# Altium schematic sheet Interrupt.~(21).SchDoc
size A; SheetNumber: 1; SheetTotal: 1
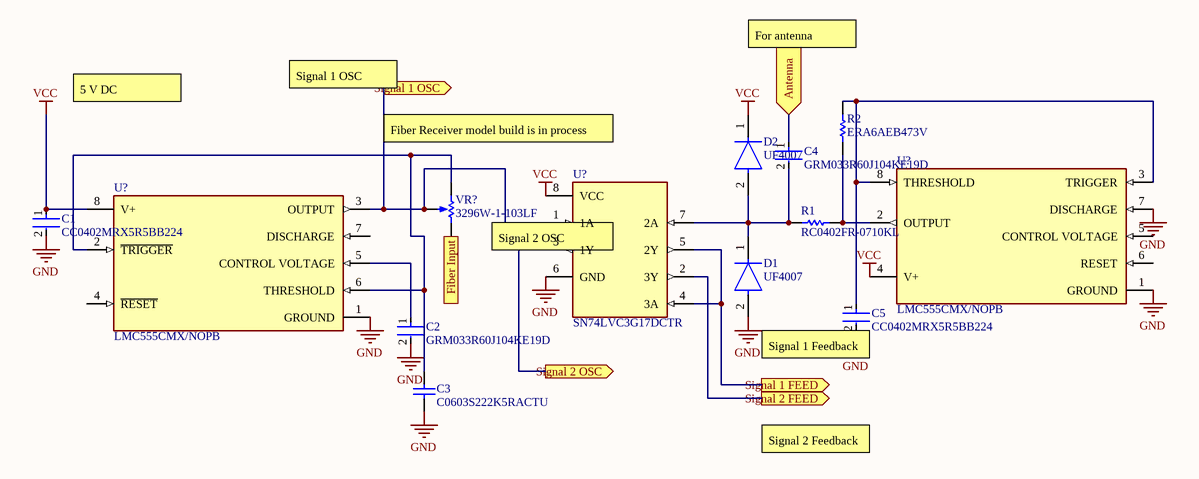
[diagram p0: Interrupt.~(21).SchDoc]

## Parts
(Parts that share a designator on the sheet are numbered #1, #2 ... from top to bottom, then left to right.)
C1  CC0402MRX5R5BB224  [FP-CC0402-MFG]
C2  GRM033R60J104KE19D  [FP-GRM033-0_03-MFG]
C3  C0603S222K5RACTU  [CAPC1608X87X35NL15T15]
C4  GRM033R60J104KE19D  [FP-GRM033-0_03-MFG]
C5  CC0402MRX5R5BB224  [FP-CC0402-MFG]
D1  UF4007  [FP-017AH-MFG]
D2  UF4007  [FP-017AH-MFG]
R1  RC0402FR-0710KL  [RESC1005X40X25LL05T10]
R2  ERA6AEB473V  [RESC2013X60X40LL20T25]
U?#1  LMC555CMX/NOPB  [FP-D0008A-MFG]
U?#2  SN74LVC3G17DCTR  [FP-DCT0008A-MFG]
U?#3  LMC555CMX/NOPB  [FP-D0008A-MFG]
VR?  3296W-1-103LF  [BOUR-3296W]

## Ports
Antenna (in), Fiber Input (in), Signal 1 FEED (out), Signal 1 OSC (out), Signal 2 FEED (out), Signal 2 OSC (out)

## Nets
GND: C1.2 C2.2 C3.1 C5.2 D1.2(A) U?#1.1(GROUND) U?#1.7(DISCHARGE) U?#2.6(GND) U?#3.1(GROUND)
VCC: C1.1 D2.1(C) U?#1.4(V+) U?#2.8(VCC) U?#3.8(V+)
Antenna: C4.1 ; port Antenna
Fiber Input: VR?.3(CW) ; port Fiber Input
Signal 1 FEED: U?#2.4(3A) U?#2.5(2Y) ; port Signal 1 FEED
Signal 1 OSC: U?#2.1(1A) U?#3.3(OUTPUT) VR?.2(S) ; port Signal 1 OSC
Signal 2 FEED: U?#2.2(3Y) ; port Signal 2 FEED
Signal 2 OSC: U?#2.3(1Y) ; port Signal 2 OSC
NetC2_1: C2.1 U?#3.5(CONTROL_VOLTAGE)
NetC3_2: C3.2 U?#3.2(~{TRIGGER}) U?#3.6(THRESHOLD) VR?.1(CCW)
NetC4_2: C4.2 D1.1(C) D2.2(A) R1.1 U?#2.7(2A)
NetC5_1: C5.1 R2.2 U?#1.3(TRIGGER) U?#1.8(THRESHOLD)
NetR1_2: R1.2 R2.1 U?#1.2(OUTPUT)

Not connected (* = marked no-connect by the designer): U?#1 5(CONTROL_VOLTAGE) 6(RESET); U?#3 4(~{RESET}) 7(DISCHARGE)

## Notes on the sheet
- For antenna
- 5 V DC
- Signal 1 OSC
- Fiber Receiver model build is in process
- (near U?#2) Signal 2 OSC
  Inverted signal output
- (near C5) Signal 1 Feedback
  (inverted)
- Signal 2 Feedback

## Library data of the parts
C1 C5 = CMP-03422-000657-1: CAP CER 0.22UF 6.3V X5R 0402; Manufacturer: YAGEO; Automotive Grade: NA; Material: Ceramic; Value: 220 nF; Tolerance: 0.2; Temperature Coefficient: 30ppm/°C
C2 = CMP-06035-000062-2: 100 nF Chip Multilayer Ceramic Capacitors for General Purpose, 0201, 0.10uF, X5R, 15%, 10%, 6.3V; Capacitance: 100nF
C3 = CMP-2006-03289-1: Manufacturer: Kemet
C4 = CMP-06035-000062-2: Chip Multilayer Ceramic Capacitors for General Purpose, 0201, 0.10uF, X5R, 15%, 10%, 6.3V; Capacitance: 100nF
D1 D2 = CMP-2000-05028-2: DIODE GEN PURP 1KV 1A DO41; Manufacturer: ON Semiconductor; Capacitance: 17pF; Max Surge Forward Current: 30A; Max Repetitive Reverse Voltage: 1000V; Value: 17pF; Max Junction Temp: +150°C; Peak Reverse Current: 10uA
R1 = CMP-2002-07353-1: 10Kohm; Manufacturer: Yageo / Phycomp
R2 = CMP-2001-00645-1: Manufacturer: Panasonic
U?#1 U?#3 = CMP-04858-000001-1: IC OSC SINGLE TIMER 3MHZ 8-SOIC; Manufacturer: Texas Instruments; Number Of Timers/Counters: 1; Max Supply Voltage: 15V; Standoff Height: 0.11mm; Propagation Delay: 100ns; Nominal Supply Current: 50-150uA; Min Supply Voltage: 1.5V
U?#2 = CMP-0859-00525-5: IC BUFFER NON-INVERT 5.5V SM8; Manufacturer: Texas Instruments; Logic Function Desc: Non-Inverting; Propagation Delay: 5.1ns; Number Of Inputs: 3; Standoff Height: 0mm; Nominal Supply Current: 10uA; Min Supply Voltage: 1.65V
VR? = CMP-1747-00001-1: Square Trimpot(R) Trimming Potentiometer, 10 KOhm, +/- 10%, 0.5 W, -55 to 125 degC, 3-Pin THD, RoHS, Tube; Voltage Rating: 75 V; Resistance: 120 Ohm; Tolerance: 1%; Power Rating: 100 mW; Case\Package: 0603; Type (Resistor): Thick Film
